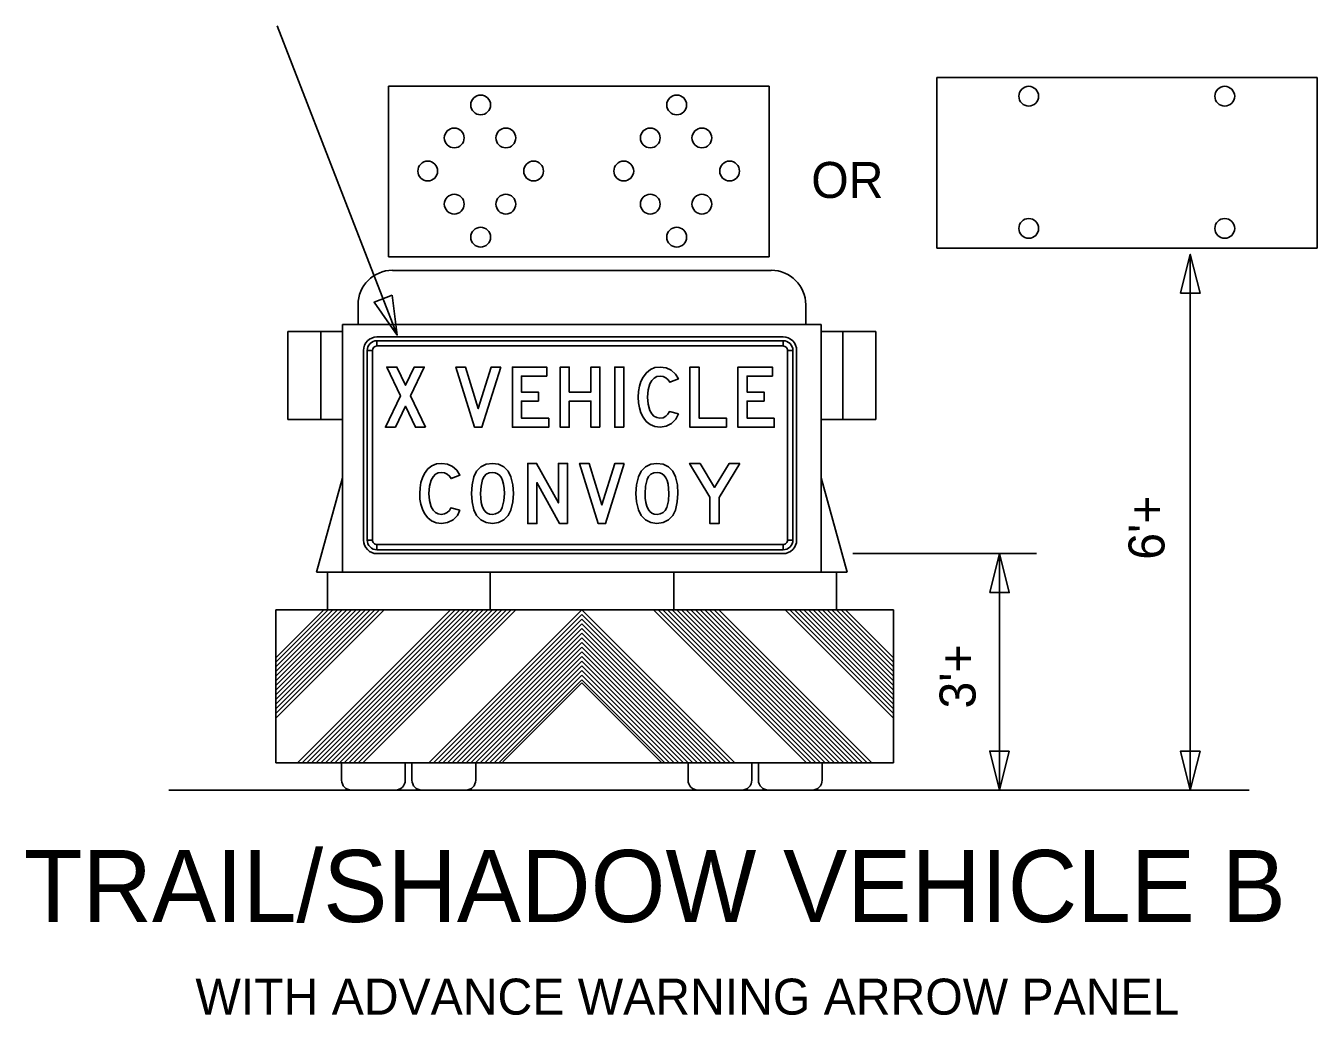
# Model space of a CAD drawing. Extents: x 1807779 to 1818251, y 673292 to 678849.
# Drawn here: x 1817416.8 to 1817632.1, y 676878.2 to 677043.1 of the extents above; entities that cross this region are included whole.
import ezdxf

# ---------------------------------------------------------------- set-up
doc = ezdxf.new("R2010")
doc.units = 0
doc.layers.add('DSN_RDWY_Drive', color=7, linetype='Continuous')

msp = doc.modelspace()

# ---------------------------------------------------------------- linework, layer by layer
at = {"layer": 'DSN_RDWY_Drive'}
for p, q in [((1817478.69, 676991.56), (1817458.68, 677043.11)), ((1817568.62, 677006.05), (1817568.62, 677034.49)), ((1817568.62, 677034.49), (1817632.05, 677034.49)), ((1817632.05, 677006.05), (1817632.05, 677034.49)), ((1817477.24, 677033.04), (1817540.67, 677033.04)), ((1817477.24, 677004.6), (1817477.24, 677033.04)), ((1817540.67, 677004.6), (1817540.67, 677033.04)), ((1817568.62, 677006.05), (1817632.05, 677006.05)), ((1817477.24, 677004.6), (1817540.67, 677004.6)), ((1817610.9, 676915.72), (1817610.9, 677005.03)), ((1817610.9, 677005.03), (1817610.9, 676999.79)), ((1817477.89, 677002.35), (1817541.03, 677002.35)), ((1817472.15, 676993.32), (1817472.15, 676996.62)), ((1817546.78, 676993.32), (1817546.78, 676996.62)), ((1817469.55, 676952.06), (1817469.55, 676993.32)), ((1817469.55, 676993.32), (1817549.38, 676993.32)), ((1817549.38, 676952.06), (1817549.38, 676993.32)), ((1817460.44, 676977.49), (1817460.44, 676992.16)), ((1817460.44, 676992.16), (1817469.55, 676992.16)), ((1817465.96, 676977.49), (1817465.96, 676992.16)), ((1817543.01, 676991.25), (1817475.3, 676991.25)), ((1817475.3, 676989.75), (1817475.3, 676990.62)), ((1817543.01, 676990.62), (1817543.01, 676989.75)), ((1817558.49, 676992.16), (1817549.38, 676992.16)), ((1817552.97, 676977.49), (1817552.97, 676992.16)), ((1817558.49, 676977.49), (1817558.49, 676992.16)), ((1817473.04, 676988.99), (1817473.04, 676957.39)), ((1817473.67, 676988.99), (1817474.54, 676988.99)), ((1817543.76, 676988.99), (1817544.64, 676988.99)), ((1817545.27, 676957.39), (1817545.27, 676988.99)), ((1817460.44, 676977.49), (1817469.55, 676977.49)), ((1817558.49, 676977.49), (1817549.38, 676977.49)), ((1817469.55, 676967.77), (1817465.23, 676952.06)), ((1817549.38, 676967.77), (1817553.7, 676952.06)), ((1817474.54, 676957.39), (1817473.67, 676957.39)), ((1817475.3, 676955.76), (1817475.3, 676956.64)), ((1817543.01, 676956.64), (1817543.01, 676955.76)), ((1817544.64, 676957.39), (1817543.76, 676957.39)), ((1817475.3, 676955.14), (1817543.01, 676955.14)), ((1817554.64, 676955.14), (1817585.26, 676955.14)), ((1817579.09, 676915.72), (1817579.09, 676955.14)), ((1817579.09, 676955.14), (1817579.09, 676949.81)), ((1817465.23, 676952.06), (1817553.7, 676952.06)), ((1817467.03, 676945.75), (1817467.03, 676952.06)), ((1817494.15, 676945.75), (1817494.15, 676951.94)), ((1817524.78, 676945.75), (1817524.78, 676951.94)), ((1817551.9, 676945.75), (1817551.9, 676952.06)), ((1817458.46, 676945.75), (1817561.41, 676945.75)), ((1817458.46, 676945.75), (1817561.41, 676945.75)), ((1817458.46, 676945.75), (1817561.41, 676945.75)), ((1817458.46, 676945.75), (1817561.41, 676945.75)), ((1817458.46, 676920.25), (1817458.46, 676945.75)), ((1817458.46, 676937.77), (1817466.44, 676945.75)), ((1817458.46, 676928.49), (1817475.72, 676945.75)), ((1817458.46, 676929.27), (1817474.94, 676945.75)), ((1817458.46, 676930.06), (1817474.15, 676945.75)), ((1817458.46, 676930.83), (1817473.38, 676945.75)), ((1817458.46, 676931.61), (1817472.6, 676945.75)), ((1817458.46, 676932.39), (1817471.82, 676945.75)), ((1817458.46, 676933.16), (1817471.05, 676945.75)), ((1817458.46, 676933.94), (1817470.27, 676945.75)), ((1817458.46, 676934.72), (1817469.49, 676945.75)), ((1817458.46, 676935.5), (1817468.71, 676945.75)), ((1817458.46, 676936.27), (1817467.94, 676945.75)), ((1817458.46, 676937.05), (1817467.16, 676945.75)), ((1817458.46, 676927.72), (1817476.47, 676945.73)), ((1817462.05, 676920.25), (1817487.55, 676945.75)), ((1817462.82, 676920.25), (1817488.32, 676945.75)), ((1817463.61, 676920.25), (1817489.1, 676945.75)), ((1817464.39, 676920.25), (1817489.88, 676945.75)), ((1817465.16, 676920.25), (1817490.65, 676945.75)), ((1817465.94, 676920.25), (1817491.44, 676945.75)), ((1817466.72, 676920.25), (1817492.22, 676945.75)), ((1817467.5, 676920.25), (1817493, 676945.75)), ((1817468.27, 676920.25), (1817493.77, 676945.75)), ((1817469.05, 676920.25), (1817494.55, 676945.75)), ((1817469.83, 676920.25), (1817495.33, 676945.75)), ((1817470.6, 676920.25), (1817496.1, 676945.75)), ((1817471.38, 676920.25), (1817496.88, 676945.75)), ((1817472.16, 676920.25), (1817497.65, 676945.74)), ((1817472.94, 676920.25), (1817498.44, 676945.75)), ((1817483.97, 676920.25), (1817509.46, 676945.75)), ((1817534.96, 676920.25), (1817509.46, 676945.75)), ((1817546.93, 676920.25), (1817521.43, 676945.75)), ((1817547.7, 676920.25), (1817522.21, 676945.74)), ((1817548.48, 676920.25), (1817522.98, 676945.75)), ((1817549.26, 676920.25), (1817523.76, 676945.75)), ((1817550.03, 676920.25), (1817524.53, 676945.75)), ((1817550.81, 676920.25), (1817525.32, 676945.75)), ((1817551.59, 676920.25), (1817526.1, 676945.75)), ((1817552.36, 676920.25), (1817526.87, 676945.75)), ((1817553.15, 676920.25), (1817527.65, 676945.75)), ((1817553.93, 676920.25), (1817528.43, 676945.75)), ((1817554.71, 676920.25), (1817529.21, 676945.75)), ((1817555.48, 676920.25), (1817529.98, 676945.75)), ((1817556.26, 676920.25), (1817530.76, 676945.75)), ((1817557.04, 676920.25), (1817531.54, 676945.75)), ((1817557.82, 676920.25), (1817532.32, 676945.75)), ((1817561.41, 676927.72), (1817543.39, 676945.73)), ((1817561.41, 676928.49), (1817544.15, 676945.75)), ((1817561.41, 676929.27), (1817544.93, 676945.75)), ((1817561.41, 676930.06), (1817545.71, 676945.75)), ((1817561.41, 676930.83), (1817546.48, 676945.75)), ((1817561.41, 676931.61), (1817547.26, 676945.75)), ((1817561.41, 676932.39), (1817548.04, 676945.75)), ((1817561.41, 676933.16), (1817548.81, 676945.75)), ((1817561.41, 676933.94), (1817549.59, 676945.75)), ((1817561.41, 676934.72), (1817550.37, 676945.75)), ((1817561.41, 676935.5), (1817551.15, 676945.75)), ((1817561.41, 676936.27), (1817551.92, 676945.75)), ((1817561.41, 676937.05), (1817552.71, 676945.75)), ((1817561.41, 676937.77), (1817553.43, 676945.75)), ((1817561.41, 676920.25), (1817561.41, 676945.75)), ((1817484.74, 676920.25), (1817509.46, 676944.98)), ((1817485.52, 676920.25), (1817509.46, 676944.2)), ((1817486.3, 676920.25), (1817509.46, 676943.42)), ((1817534.15, 676920.3), (1817509.46, 676944.98)), ((1817533.41, 676920.25), (1817509.46, 676944.2)), ((1817532.63, 676920.25), (1817509.46, 676943.42)), ((1817487.07, 676920.25), (1817509.46, 676942.65)), ((1817487.86, 676920.25), (1817509.46, 676941.86)), ((1817488.64, 676920.25), (1817509.46, 676941.08)), ((1817531.86, 676920.25), (1817509.46, 676942.65)), ((1817531.08, 676920.25), (1817509.46, 676941.86)), ((1817530.3, 676920.25), (1817509.46, 676941.08)), ((1817489.41, 676920.25), (1817509.46, 676940.31)), ((1817490.19, 676920.25), (1817509.46, 676939.53)), ((1817529.53, 676920.25), (1817509.46, 676940.31)), ((1817528.75, 676920.25), (1817509.46, 676939.53)), ((1817490.97, 676920.25), (1817509.46, 676938.75)), ((1817491.75, 676920.25), (1817509.46, 676937.97)), ((1817492.52, 676920.25), (1817509.46, 676937.2)), ((1817527.97, 676920.25), (1817509.46, 676938.75)), ((1817527.19, 676920.25), (1817509.46, 676937.97)), ((1817526.42, 676920.25), (1817509.46, 676937.2)), ((1817493.3, 676920.25), (1817509.46, 676936.42)), ((1817494.08, 676920.25), (1817509.46, 676935.64)), ((1817494.85, 676920.25), (1817509.46, 676934.87)), ((1817525.63, 676920.25), (1817509.46, 676936.42)), ((1817524.85, 676920.25), (1817509.46, 676935.64)), ((1817524.08, 676920.25), (1817509.46, 676934.87)), ((1817495.63, 676920.25), (1817509.46, 676934.09)), ((1817496.28, 676920.4), (1817509.46, 676933.59)), ((1817523.3, 676920.25), (1817509.46, 676934.09)), ((1817522.8, 676920.25), (1817509.46, 676933.59)), ((1817458.46, 676920.25), (1817561.41, 676920.25)), ((1817458.46, 676920.25), (1817561.41, 676920.25)), ((1817458.46, 676920.25), (1817561.41, 676920.25)), ((1817458.46, 676920.25), (1817561.41, 676920.25)), ((1817469.4, 676917.37), (1817469.4, 676920.25)), ((1817480.03, 676917.37), (1817480.03, 676920.25)), ((1817481.13, 676917.37), (1817481.13, 676920.25)), ((1817491.77, 676917.37), (1817491.77, 676920.25)), ((1817527.16, 676917.37), (1817527.16, 676920.25)), ((1817537.8, 676917.37), (1817537.8, 676920.25)), ((1817538.9, 676917.37), (1817538.9, 676920.25)), ((1817549.53, 676917.37), (1817549.53, 676920.25)), ((1817440.58, 676915.72), (1817620.69, 676915.72)), ((1817469.4, 676915.72), (1817480.03, 676915.72)), ((1817469.4, 676915.72), (1817480.03, 676915.72)), ((1817469.4, 676915.72), (1817480.03, 676915.72)), ((1817469.4, 676915.72), (1817480.03, 676915.72)), ((1817481.13, 676915.72), (1817491.77, 676915.72)), ((1817481.13, 676915.72), (1817491.77, 676915.72)), ((1817481.13, 676915.72), (1817491.77, 676915.72)), ((1817481.13, 676915.72), (1817491.77, 676915.72)), ((1817537.8, 676915.72), (1817527.16, 676915.72)), ((1817537.8, 676915.72), (1817527.16, 676915.72)), ((1817537.8, 676915.72), (1817527.16, 676915.72)), ((1817537.8, 676915.72), (1817527.16, 676915.72)), ((1817549.53, 676915.72), (1817538.9, 676915.72)), ((1817549.53, 676915.72), (1817538.9, 676915.72)), ((1817549.53, 676915.72), (1817538.9, 676915.72)), ((1817549.53, 676915.72), (1817538.9, 676915.72))]:
    msp.add_line(p, q, dxfattribs=at)
for points in [[(1817609.27, 676998.53), (1817610.9, 677005.03), (1817612.52, 676998.53)], [(1817477.86, 676998.21), (1817478.69, 676991.56), (1817474.83, 676997.04)], [(1817543.01, 676990.62), (1817475.3, 676990.62), (1817475.3, 676989.75), (1817543.01, 676989.75), (1817543.01, 676990.62)], [(1817473.67, 676988.99), (1817473.67, 676957.39), (1817474.54, 676957.39), (1817474.54, 676988.99), (1817473.67, 676988.99)], [(1817544.64, 676957.39), (1817544.64, 676988.99), (1817543.76, 676988.99), (1817543.76, 676957.39), (1817544.64, 676957.39)], [(1817483.4, 676976.2), (1817480.9, 676981.46), (1817483.19, 676986.23), (1817481.52, 676986.23), (1817480.06, 676983.21), (1817478.62, 676986.23), (1817476.94, 676986.23), (1817479.22, 676981.45), (1817476.71, 676976.2), (1817478.38, 676976.2), (1817480.06, 676979.69), (1817481.72, 676976.2)], [(1817495.93, 676986.23), (1817494.35, 676986.23), (1817492.19, 676979.3), (1817490.04, 676986.23), (1817488.46, 676986.23), (1817491.57, 676976.2), (1817492.81, 676976.2)], [(1817503.93, 676977.72), (1817499.38, 676977.72), (1817499.38, 676980.56), (1817502.22, 676980.56), (1817502.22, 676982.07), (1817499.38, 676982.07), (1817499.38, 676984.72), (1817503.62, 676984.72), (1817503.62, 676986.23), (1817497.87, 676986.23), (1817497.87, 676976.2), (1817503.93, 676976.2)], [(1817512.48, 676976.2), (1817512.48, 676986.23), (1817510.97, 676986.23), (1817510.97, 676982.07), (1817507.37, 676982.07), (1817507.37, 676986.23), (1817505.86, 676986.23), (1817505.86, 676976.2), (1817507.37, 676976.2), (1817507.37, 676980.56), (1817510.97, 676980.56), (1817510.97, 676976.2)], [(1817516.47, 676976.2), (1817516.47, 676986.23), (1817514.95, 676986.23), (1817514.95, 676976.2)], [(1817525.57, 676978.43), (1817524.05, 676978.81), (1817523.82, 676978.37), (1817523.46, 676978.02), (1817522.99, 676977.79), (1817522.46, 676977.72), (1817521.94, 676977.8), (1817521.48, 676978.04), (1817521.1, 676978.44), (1817520.8, 676978.99), (1817520.49, 676980.02), (1817520.38, 676981.22), (1817520.49, 676982.42), (1817520.81, 676983.45), (1817521.12, 676984), (1817521.51, 676984.4), (1817521.98, 676984.64), (1817522.51, 676984.72), (1817523.01, 676984.65), (1817523.47, 676984.44), (1817523.85, 676984.11), (1817524.11, 676983.69), (1817525.57, 676984.26), (1817525.07, 676985.07), (1817524.36, 676985.7), (1817523.49, 676986.1), (1817522.54, 676986.23), (1817521.65, 676986.13), (1817520.88, 676985.81), (1817520.23, 676985.29), (1817519.68, 676984.56), (1817519.32, 676983.84), (1817519.07, 676983.04), (1817518.92, 676982.17), (1817518.87, 676981.22), (1817518.92, 676980.28), (1817519.07, 676979.41), (1817519.32, 676978.62), (1817519.67, 676977.89), (1817520.2, 676977.15), (1817520.85, 676976.63), (1817521.62, 676976.31), (1817522.49, 676976.2), (1817523.51, 676976.36), (1817524.42, 676976.82), (1817525.14, 676977.53)], [(1817533.56, 676976.2), (1817533.56, 676977.72), (1817529.01, 676977.72), (1817529.01, 676986.23), (1817527.49, 676986.23), (1817527.49, 676976.2)], [(1817541.55, 676977.72), (1817537, 676977.72), (1817537, 676980.56), (1817539.84, 676980.56), (1817539.84, 676982.07), (1817537, 676982.07), (1817537, 676984.72), (1817541.24, 676984.72), (1817541.24, 676986.23), (1817535.49, 676986.23), (1817535.49, 676976.2), (1817541.55, 676976.2)], [(1817489.12, 676962.38), (1817487.6, 676962.76), (1817487.38, 676962.32), (1817487.01, 676961.97), (1817486.54, 676961.74), (1817486.02, 676961.67), (1817485.49, 676961.75), (1817485.04, 676961.99), (1817484.66, 676962.38), (1817484.35, 676962.94), (1817484.04, 676963.97), (1817483.94, 676965.17), (1817484.04, 676966.37), (1817484.36, 676967.4), (1817484.68, 676967.95), (1817485.07, 676968.35), (1817485.53, 676968.59), (1817486.07, 676968.67), (1817486.57, 676968.6), (1817487.03, 676968.39), (1817487.41, 676968.06), (1817487.67, 676967.64), (1817489.12, 676968.21), (1817488.63, 676969.02), (1817487.92, 676969.65), (1817487.05, 676970.05), (1817486.09, 676970.18), (1817485.21, 676970.08), (1817484.44, 676969.76), (1817483.78, 676969.24), (1817483.23, 676968.51), (1817482.88, 676967.79), (1817482.63, 676966.99), (1817482.48, 676966.12), (1817482.43, 676965.17), (1817482.47, 676964.23), (1817482.62, 676963.36), (1817482.87, 676962.56), (1817483.23, 676961.84), (1817483.76, 676961.1), (1817484.41, 676960.57), (1817485.17, 676960.26), (1817486.04, 676960.15), (1817487.06, 676960.31), (1817487.98, 676960.77), (1817488.7, 676961.48)], [(1817498.05, 676965.17), (1817497.95, 676966.6), (1817497.64, 676967.94), (1817497.19, 676968.85), (1817496.47, 676969.57), (1817495.56, 676970.03), (1817494.54, 676970.18), (1817493.52, 676970.03), (1817492.62, 676969.57), (1817491.9, 676968.85), (1817491.46, 676967.94), (1817491.15, 676966.6), (1817491.05, 676965.17), (1817491.15, 676963.75), (1817491.46, 676962.41), (1817491.9, 676961.5), (1817492.62, 676960.78), (1817493.52, 676960.31), (1817494.54, 676960.15), (1817495.56, 676960.31), (1817496.47, 676960.77), (1817497.18, 676961.48), (1817497.63, 676962.39), (1817497.94, 676963.74)], [(1817507.08, 676960.15), (1817507.08, 676970.18), (1817505.56, 676970.18), (1817505.56, 676963.59), (1817501.91, 676970.18), (1817500.45, 676970.18), (1817500.45, 676960.15), (1817501.97, 676960.15), (1817501.97, 676966.96), (1817505.74, 676960.15)], [(1817516.54, 676970.18), (1817514.96, 676970.18), (1817512.81, 676963.25), (1817510.66, 676970.18), (1817509.07, 676970.18), (1817512.18, 676960.15), (1817513.43, 676960.15)], [(1817525.48, 676965.17), (1817525.38, 676966.6), (1817525.07, 676967.94), (1817524.62, 676968.85), (1817523.9, 676969.57), (1817522.99, 676970.03), (1817521.97, 676970.18), (1817520.95, 676970.03), (1817520.05, 676969.57), (1817519.34, 676968.85), (1817518.89, 676967.94), (1817518.58, 676966.6), (1817518.48, 676965.17), (1817518.58, 676963.75), (1817518.89, 676962.41), (1817519.34, 676961.5), (1817520.05, 676960.78), (1817520.95, 676960.31), (1817521.97, 676960.15), (1817522.99, 676960.31), (1817523.9, 676960.77), (1817524.61, 676961.48), (1817525.06, 676962.39), (1817525.37, 676963.74)], [(1817535.82, 676970.18), (1817534.04, 676970.18), (1817531.58, 676966.18), (1817529.18, 676970.18), (1817527.41, 676970.18), (1817530.82, 676964.55), (1817530.82, 676960.15), (1817532.33, 676960.15), (1817532.33, 676964.51)], [(1817496.54, 676965.17), (1817496.45, 676963.95), (1817496.18, 676962.82), (1817495.94, 676962.34), (1817495.56, 676961.98), (1817495.09, 676961.74), (1817494.55, 676961.67), (1817494.08, 676961.72), (1817493.68, 676961.89), (1817493.34, 676962.16), (1817493.06, 676962.54), (1817492.84, 676963.03), (1817492.69, 676963.64), (1817492.59, 676964.35), (1817492.56, 676965.17), (1817492.65, 676966.38), (1817492.92, 676967.51), (1817493.16, 676967.98), (1817493.53, 676968.35), (1817494.01, 676968.59), (1817494.55, 676968.67), (1817495.02, 676968.61), (1817495.42, 676968.45), (1817495.76, 676968.18), (1817496.04, 676967.79), (1817496.25, 676967.3), (1817496.41, 676966.7), (1817496.5, 676965.99)], [(1817523.97, 676965.17), (1817523.88, 676963.95), (1817523.61, 676962.82), (1817523.37, 676962.34), (1817522.99, 676961.98), (1817522.52, 676961.74), (1817521.99, 676961.67), (1817521.52, 676961.72), (1817521.11, 676961.89), (1817520.77, 676962.16), (1817520.49, 676962.54), (1817520.27, 676963.03), (1817520.12, 676963.64), (1817520.02, 676964.35), (1817519.99, 676965.17), (1817520.08, 676966.38), (1817520.35, 676967.51), (1817520.59, 676967.98), (1817520.96, 676968.35), (1817521.44, 676968.59), (1817521.99, 676968.67), (1817522.45, 676968.61), (1817522.85, 676968.45), (1817523.19, 676968.18), (1817523.47, 676967.79), (1817523.69, 676967.3), (1817523.84, 676966.7), (1817523.93, 676965.99)], [(1817475.3, 676955.76), (1817543.01, 676955.76), (1817543.01, 676956.64), (1817475.3, 676956.64), (1817475.3, 676955.76)], [(1817577.46, 676948.64), (1817579.09, 676955.14), (1817580.71, 676948.64)], [(1817580.71, 676922.22), (1817579.09, 676915.72), (1817577.46, 676922.22)], [(1817612.52, 676922.22), (1817610.9, 676915.72), (1817609.27, 676922.22)]]:
    msp.add_lwpolyline(points, close=True, dxfattribs=at)
for centre in [(1817492.59, 677029.93), (1817525.27, 677029.93), (1817583.97, 677031.38), (1817616.65, 677031.38), (1817488.18, 677024.42), (1817496.79, 677024.42), (1817520.86, 677024.42), (1817529.47, 677024.42), (1817483.77, 677018.91), (1817501.41, 677018.91), (1817516.45, 677018.91), (1817534.09, 677018.91), (1817488.18, 677013.39), (1817496.79, 677013.39), (1817520.86, 677013.39), (1817529.47, 677013.39), (1817583.97, 677009.34), (1817616.65, 677009.34), (1817492.59, 677007.88), (1817525.27, 677007.88)]:
    msp.add_circle(centre, 1.65, dxfattribs=at)
for centre, radius, start, end in [((1817477.89, 676996.62), 5.74, 90, 180), ((1817541.04, 676996.62), 5.74, 0, 90), ((1817475.3, 676988.99), 2.26, 90.0002, 179.9998), ((1817475.3, 676988.99), 1.63, 90.0002, 179.9998), ((1817543.01, 676988.99), 2.26, 0, 90.0002), ((1817543.01, 676988.99), 1.63, 0, 90.0002), ((1817475.3, 676988.99), 0.752, 90.0002, 179.9998), ((1817543.01, 676988.99), 0.752, 0, 90.0002), ((1817475.3, 676957.39), 2.26, 179.9998, 270.0001), ((1817475.3, 676957.39), 1.63, 179.9998, 270.0001), ((1817475.3, 676957.39), 0.752, 179.9998, 270.0001), ((1817543.01, 676957.39), 2.26, 270.0001, 0.0003), ((1817543.01, 676957.39), 1.63, 270.0001, 0.0003), ((1817543.01, 676957.39), 0.752, 270.0001, 0.0003), ((1817471.05, 676917.37), 1.65, 180, 270), ((1817478.38, 676917.37), 1.65, 270, 0), ((1817482.78, 676917.37), 1.65, 180, 270), ((1817490.12, 676917.37), 1.65, 270, 0), ((1817528.81, 676917.37), 1.65, 180, 270), ((1817536.15, 676917.37), 1.65, 270, 0), ((1817540.55, 676917.37), 1.65, 180, 270), ((1817547.88, 676917.37), 1.65, 270, 0)]:
    msp.add_arc(centre, radius, start, end, dxfattribs=at)

# ---------------------------------------------------------------- texts
for s, height, p in [('OR', 6, (1817547.71, 677014.42)), ('TRAIL/SHADOW VEHICLE B', 12, (1817416.4, 676893.72)), ('WITH ADVANCE WARNING ARROW PANEL', 6, (1817445.03, 676878.28))]:
    msp.add_text(s, height=height, dxfattribs=at).set_placement(p)
for s, p in [("6'+", (1817606.6, 676954.11)), ("3'+", (1817575.1, 676929.31))]:
    msp.add_text(s, height=6, rotation=90, dxfattribs=at).set_placement(p)

doc.saveas('drawing.dxf')
